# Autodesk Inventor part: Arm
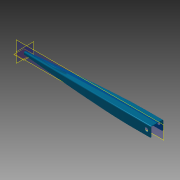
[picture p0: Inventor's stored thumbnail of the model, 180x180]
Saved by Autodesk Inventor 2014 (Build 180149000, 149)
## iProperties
Created: 2006-03
Part Number: Arm
Document SubType Name: Modeling
Designer: debonom
Material: Stainless Steel, 440C
Mass: 106.754 g
Surface Area: 286.718 cm^2
Volume: 13.7747 cm^3
Density: 7.75 g/cm^3
Appearance: Sky Blue Dark
Author: debonom
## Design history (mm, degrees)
sketch "Sketch1"
  geometry: L1 (-13.5, 11)-(13.5, 11); L2 (13.5, 11)-(13.5, -11); L3 (13.5, -11)-(-13.5, -11); L4 (-13.5, -11)-(-13.5, 11); L5 (-13.5, 11)-(13.5, -11); 2 further points
  constraints: 10 end point, 2 parallel, 1 coincident, 1 horizontal, 1 midpoint, 1 perpendicular
  dimensions: "d0" = 27 distance of L1.start L1.end; "d1" = 22 distance of L3.end L1.start
extrude "Extrusion1" new body sketch "Sketch1" distance "d2" = 40; taper "d3" = 0 deg
workplane "Work Plane1"
sketch "Sketch2"
  geometry: L1 (-2.5, 2.5)-(2.5, 2.5); L2 (2.5, 2.5)-(2.5, -2.5); L3 (2.5, -2.5)-(-2.5, -2.5); L4 (-2.5, -2.5)-(-2.5, 2.5); L5 (-2.5, 2.5)-(2.5, -2.5); 2 further points
  constraints: 10 end point, 2 parallel, 2 perpendicular, 1 coincident, 1 horizontal, 1 midpoint
  dimensions: "d5" = 5 distance of L1.start L1.end
loft "Loft1" sketch "Sketch2" dims "d6" = 10, "d7" = 90 deg, "d8" = 10, "d9" = 90 deg
  node "Edges1"
shell "Shell1" dims "d10" = 1
sketch "Sketch3"
  geometry: L1 (-48, 0)-(8, 0) reference; L2 (-40, 10)-(-40, -11) reference; C1 r 4 at (-30, 0); 1 further point
  constraints: 1 centre point, 1 point on line
  dimensions: "d11" = 10 distance from line of C1.centre L2; "d16" = 8 diameter of C1
extrude "Extrusion2" cut sketch "Sketch3" stored distance "d12" = 40; taper "d13" = 0 deg
fillet "Fillet1" dims "d14" = 2
fillet "Fillet2" dims "d15" = 2
workplane "Work Plane2"
workplane "Work Plane3"
body "Solid1"
